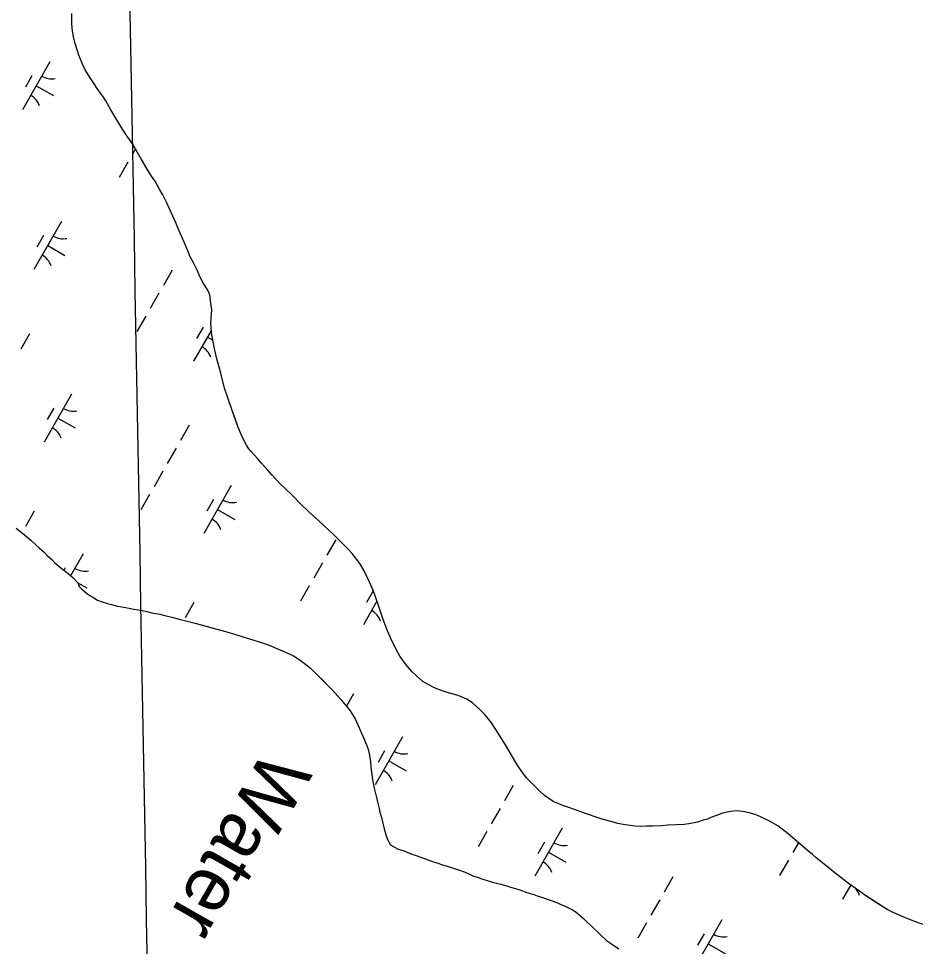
# Model space of a CAD drawing. Extents: x 3930721 to 3950824, y 220441 to 242861.
# Drawn here: x 3940727 to 3941538, y 225412 to 226251 of the extents above; entities that cross this region are included whole.
import ezdxf

# ---------------------------------------------------------------- set-up
doc = ezdxf.new("R2010")
doc.units = 0
for name, color, linetype in [('V-GRID-MAJR', 7, 'Continuous'), ('V-RIVR-IDEN', 7, 'Continuous'), ('V-TOPO-SHOR', 7, 'Continuous'), ('V-WETL-SWMP', 7, 'Continuous')]:
    doc.layers.add(name, color=color, linetype=linetype)

msp = doc.modelspace()

# ---------------------------------------------------------------- linework, layer by layer
at = {"layer": 'V-GRID-MAJR'}
msp.add_spline([(3940914.45, 221486.32), (3940866.25, 224158.18), (3940756.95, 230218.14), (3940647.64, 236278.08), (3940604.74, 238656.84)], degree=3, dxfattribs=at)
at = {"layer": 'V-TOPO-SHOR'}
for points in [[(3940937.64, 225859.68), (3940935.6, 225861.9), (3940933.36, 225865.33), (3940929.68, 225872.79), (3940925.58, 225882.08), (3940923.12, 225889.35), (3940920.65, 225896.62), (3940916.34, 225908.93), (3940913.67, 225916.81), (3940910.16, 225930.35), (3940906.44, 225944.49), (3940904.37, 225953.79), (3940901.87, 225966.92), (3940901.21, 225976.03), (3940902.16, 225987.77), (3940900.91, 225995.85), (3940900.27, 226001.11), (3940899.04, 226004.14), (3940897.21, 226007.36), (3940895.17, 226010.39), (3940893.33, 226013.61), (3940890.67, 226019.27), (3940888.83, 226023.51), (3940885.35, 226030.77), (3940882.69, 226035.61), (3940880.44, 226040.86), (3940877.16, 226048.73), (3940873.88, 226056.2), (3940871.63, 226061.24), (3940869.79, 226065.69), (3940866.92, 226072.35), (3940863.65, 226079.41), (3940861.39, 226084.26), (3940857.71, 226091.72), (3940855.26, 226096.16), (3940850.77, 226103.82), (3940847.71, 226108.46), (3940843.63, 226114.92), (3940838.32, 226124.19), (3940833.83, 226132.06), (3940830.36, 226137.71), (3940824.04, 226146.78), (3940819.96, 226153.23), (3940814.45, 226162.51), (3940810.77, 226168.35), (3940806.28, 226176.42), (3940803.63, 226180.66), (3940799.15, 226186.7), (3940795.07, 226192.95), (3940792.21, 226197.39), (3940787.72, 226204.65), (3940785.27, 226209.69), (3940781.79, 226217.77), (3940778.69, 226228.27), (3940777.46, 226233.32), (3940776.21, 226239.59), (3940775.57, 226246.06), (3940775.54, 226250.11), (3940775.72, 226255.57)], [(3941119.46, 225640.52), (3941113.99, 225642.11), (3941107.1, 225644.51), (3941102.84, 225646.1), (3941096.96, 225649.11), (3941092.9, 225651.51), (3941087.21, 225656.74), (3941083.14, 225660.36), (3941077.65, 225666.61), (3941072.14, 225674.47), (3941068.88, 225680.72), (3941063.97, 225690.61), (3941060.9, 225697.47), (3941057, 225707.77), (3941054.53, 225715.04), (3941052.06, 225722.31), (3941048.16, 225733.21), (3941045.09, 225740.89), (3941039.77, 225751.78), (3941035.89, 225758.44), (3941028.97, 225767.3), (3941024.49, 225772.14), (3941016.96, 225779.58), (3941011.68, 225784.81), (3941003.95, 225792.06), (3940998.46, 225797.09), (3940990.13, 225804.73), (3940981.59, 225812.98), (3940975.89, 225818.82), (3940967.15, 225827.27), (3940964.3, 225830.08), (3940956.57, 225838.14), (3940952.5, 225842.97), (3940947, 225849.01), (3940943.34, 225853.24), (3940940.49, 225856.66), (3940937.64, 225859.68)], [(3940725.37, 225790.38), (3940731.06, 225785.76), (3940734.72, 225782.74), (3940738.38, 225779.53), (3940743.05, 225775.1), (3940746.1, 225772.49), (3940750.57, 225768.46), (3940753.42, 225765.65), (3940757.69, 225761.62), (3940760.34, 225759.01), (3940765.62, 225754.38), (3940772.12, 225749.15), (3940776.39, 225745.54), (3940780.87, 225740.7), (3940782.3, 225737.68), (3940784.33, 225735.46), (3940788.8, 225731.64), (3940791.85, 225729.43), (3940794.49, 225727.83), (3940798.75, 225725.22), (3940801.99, 225724.02), (3940807.67, 225722.23), (3940811.32, 225721.24), (3940816.99, 225719.85), (3940820.84, 225719.06), (3940827.52, 225717.89), (3940831.77, 225717.1), (3940836.23, 225716.31), (3940843.52, 225714.94), (3940847.97, 225713.74), (3940855.06, 225712.37), (3940859.72, 225711.18), (3940867.22, 225709.4), (3940872.48, 225708.01), (3940880.99, 225706.03)], [(3940880.99, 225706.03), (3940887.07, 225704.24), (3940896.8, 225701.66), (3940906.52, 225699.08), (3940912.4, 225697.5), (3940920.71, 225695.11), (3940931.04, 225691.73), (3940936.11, 225690.14), (3940944.01, 225687.75), (3940951.1, 225685.36), (3940955.56, 225683.76), (3940961.44, 225681.17), (3940965.5, 225679.57), (3940971.99, 225676.57), (3940976.04, 225674.77), (3940981.93, 225670.96), (3940985.59, 225668.14), (3940990.87, 225663.92), (3940994.12, 225660.9), (3940998.8, 225656.28), (3941002.06, 225653.05), (3941005.31, 225649.83), (3941010.19, 225644.8), (3941013.65, 225640.98), (3941018.74, 225635.34), (3941023.62, 225629.7), (3941027.09, 225625.27), (3941031.58, 225617.81), (3941034.23, 225612.56), (3941037.51, 225604.89), (3941039.97, 225599.44), (3941043.05, 225591.36), (3941044.49, 225586.31), (3941045.54, 225579.44), (3941045.97, 225574.58), (3941046.4, 225569.33), (3941047.66, 225560.84), (3941048.9, 225555.18), (3941050.97, 225546.9), (3941052, 225542.86), (3941053.45, 225536.99), (3941054.08, 225533.56), (3941055.52, 225528.71), (3941056.35, 225524.87), (3941057.8, 225518.4), (3941059.65, 225512.14), (3941061.09, 225508.11), (3941063.74, 225503.87), (3941069.83, 225500.46), (3941076.72, 225498.27), (3941082.8, 225495.68), (3941086.85, 225494.28), (3941091.72, 225492.69), (3941095.17, 225491.29), (3941100.64, 225489.3), (3941104.49, 225488.1), (3941111.58, 225485.71), (3941116.85, 225484.12), (3941124.15, 225481.73), (3941131.04, 225479.34), (3941134.48, 225477.74), (3941138.14, 225475.94), (3941142.8, 225474.35), (3941147.05, 225472.95), (3941151.11, 225471.76), (3941155.97, 225470.17), (3941159.42, 225469.38), (3941163.26, 225468.59), (3941168.74, 225466.8), (3941172.18, 225465.8), (3941176.64, 225464.41), (3941180.49, 225463.21), (3941186.77, 225461.02), (3941193.05, 225459.03), (3941196.1, 225457.83), (3941201.16, 225456.24), (3941206.23, 225454.45), (3941209.67, 225453.25), (3941214.54, 225451.46), (3941217.58, 225450.06), (3941221.43, 225448.66), (3941228.13, 225445.26), (3941231.38, 225443.05), (3941235.64, 225439.43), (3941238.08, 225437.42), (3941241.54, 225434), (3941243.98, 225431.79), (3941246.42, 225429.37), (3941250.49, 225425.75), (3941253.54, 225422.73), (3941259.02, 225417.5), (3941263.29, 225414.49), (3941269.99, 225410.07)], [(3941467.1, 225477.07), (3941462.22, 225481.09), (3941457.34, 225485.11), (3941451.25, 225490.14), (3941448.4, 225492.15), (3941444.95, 225495.36), (3941440.27, 225499.18), (3941437.83, 225501.4), (3941433.97, 225504.61), (3941429.3, 225508.43), (3941423.2, 225513.86), (3941420.36, 225516.07), (3941416.5, 225519.09), (3941413.65, 225521.3), (3941406.15, 225525.3), (3941402.7, 225527.1), (3941397.42, 225529.71), (3941393.17, 225531.3), (3941387.7, 225532.89), (3941383.65, 225533.88), (3941377.17, 225534.66), (3941371.1, 225534.02), (3941367.87, 225533.6), (3941363.82, 225532.77), (3941358.37, 225530.51), (3941353.32, 225528.67), (3941350.09, 225527.23), (3941346.26, 225526.2), (3941341, 225524.55), (3941333.32, 225523.1), (3941329.08, 225522.27), (3941322, 225522.02), (3941314.31, 225521.78), (3941308.65, 225521.15), (3941300.36, 225520.9), (3941294.9, 225520.87), (3941289.64, 225520.64), (3941284.38, 225520.82), (3941273.85, 225522.38), (3941268.99, 225523.36), (3941264.12, 225524.76), (3941256.02, 225526.94), (3941250.35, 225528.73), (3941241.63, 225531.72), (3941235.55, 225533.91), (3941225.82, 225537.3), (3941219.54, 225539.49), (3941210.62, 225543.29), (3941202.7, 225548.71), (3941198.43, 225552.73), (3941191.31, 225559.78), (3941186.63, 225564.61), (3941182.35, 225570.25), (3941178.27, 225576.3), (3941172.76, 225585.58), (3941167.45, 225594.45), (3941163.98, 225600.1), (3941158.88, 225608.36), (3941155.01, 225614.21), (3941149.1, 225621.46), (3941144.83, 225626.09), (3941137.71, 225632.33), (3941132.64, 225635.54), (3941124.73, 225638.93), (3941119.46, 225640.52)], [(3941614.31, 225413.51), (3941604.79, 225415.48), (3941597.91, 225416.86), (3941587.57, 225419.64), (3941580.48, 225421.42), (3941570.15, 225424.2), (3941560.83, 225426.78), (3941554.75, 225428.57), (3941546.44, 225431.56), (3941540.56, 225433.56), (3941532.05, 225436.95), (3941529.21, 225437.95), (3941518.06, 225442.95), (3941513.19, 225445.14), (3941509.13, 225447.55), (3941503.04, 225451.57), (3941498.78, 225454.38), (3941492.08, 225458.79), (3941487.61, 225462), (3941480.7, 225467.02), (3941476.24, 225470.24), (3941470.75, 225474.46), (3941467.1, 225477.07)]]:
    msp.add_lwpolyline(points, dxfattribs=at)
at = {"layer": 'V-WETL-SWMP'}
for p, q in [((3940755.71, 226211.91), (3940730.86, 226168.52)), ((3940739.57, 226199.26), (3940733.61, 226188.84)), ((3940743.29, 226190.22), (3940758.91, 226181.27)), ((3940833.13, 226133.19), (3940830.27, 226128.21)), ((3940826.3, 226121.26), (3940818.35, 226107.38)), ((3940766.18, 226067.35), (3940741.34, 226023.96)), ((3940750.05, 226054.7), (3940744.08, 226044.29)), ((3940753.76, 226045.66), (3940769.38, 226036.71)), ((3940866.26, 226023.53), (3940858.31, 226009.64)), ((3940854.33, 226002.7), (3940846.38, 225988.82)), ((3940842.4, 225981.87), (3940834.45, 225967.99)), ((3940894.39, 225972.03), (3940888.42, 225961.62)), ((3940737.36, 225965.97), (3940729.41, 225952.09)), ((3940901.7, 225969.28), (3940885.68, 225941.3)), ((3940898.1, 225962.99), (3940903.17, 225960.09)), ((3940775.33, 225911.47), (3940750.48, 225868.09)), ((3940759.2, 225898.82), (3940753.23, 225888.41)), ((3940762.91, 225889.78), (3940778.53, 225880.84)), ((3940881.7, 225883.31), (3940873.75, 225869.42)), ((3940869.78, 225862.48), (3940861.82, 225848.6)), ((3940857.85, 225841.66), (3940849.9, 225827.77)), ((3940845.92, 225820.83), (3940837.97, 225806.95)), ((3940919.67, 225828.81), (3940894.83, 225785.42)), ((3940903.54, 225816.16), (3940897.57, 225805.74)), ((3940741.54, 225805.76), (3940733.59, 225791.87)), ((3940907.25, 225807.11), (3940922.87, 225798.17)), ((3941014.12, 225779.82), (3941006.17, 225765.93)), ((3940785.81, 225766.92), (3940774.49, 225747.15)), ((3940769.67, 225754.26), (3940768.44, 225752.11)), ((3941002.19, 225758.99), (3940994.24, 225745.11)), ((3940780.4, 225741.2), (3940789, 225736.28)), ((3940990.26, 225738.16), (3940982.31, 225724.28)), ((3941047.88, 225733.49), (3941041.91, 225723.08)), ((3940885.88, 225723.09), (3940877.93, 225709.21)), ((3941051.41, 225724.13), (3941039.17, 225702.75)), ((3941030.22, 225640.43), (3941023.89, 225629.36)), ((3941074.49, 225601.59), (3941049.64, 225558.2)), ((3941058.35, 225588.93), (3941052.39, 225578.52)), ((3941062.07, 225579.89), (3941077.69, 225570.95)), ((3941174.56, 225557.76), (3941166.61, 225543.87)), ((3941162.64, 225536.93), (3941154.69, 225523.05)), ((3941218.83, 225518.92), (3941193.98, 225475.53)), ((3941150.71, 225516.11), (3941142.76, 225502.22)), ((3941202.69, 225506.27), (3941196.73, 225495.85)), ((3941432.33, 225505.95), (3941427.26, 225497.11)), ((3941206.41, 225497.23), (3941222.03, 225488.28)), ((3941423.29, 225490.17), (3941415.33, 225476.28)), ((3941318.91, 225475.09), (3941310.95, 225461.21)), ((3941479.65, 225467.78), (3941472.19, 225454.76)), ((3941306.98, 225454.27), (3941299.03, 225440.38)), ((3941363.17, 225436.25), (3941338.32, 225392.86)), ((3941295.05, 225433.44), (3941287.1, 225419.56)), ((3941347.04, 225423.6), (3941341.07, 225413.19)), ((3941350.75, 225414.56), (3941366.37, 225405.61))]:
    msp.add_line(p, q, dxfattribs=at)
for points in [[(3940857.71, 226091.72), (3940855.26, 226096.16), (3940850.77, 226103.82), (3940847.71, 226108.46), (3940843.63, 226114.91), (3940838.32, 226124.19), (3940833.83, 226132.06), (3940830.36, 226137.71), (3940824.04, 226146.78), (3940819.96, 226153.23), (3940814.45, 226162.51), (3940810.77, 226168.35), (3940806.28, 226176.42), (3940803.63, 226180.66), (3940799.15, 226186.7), (3940795.07, 226192.95), (3940792.21, 226197.39), (3940787.72, 226204.65), (3940785.27, 226209.69), (3940781.79, 226217.77), (3940778.7, 226228.27), (3940777.46, 226233.32), (3940776.21, 226239.59), (3940775.57, 226246.06), (3940775.54, 226250.11), (3940775.72, 226255.57)], [(3941329.08, 225522.27), (3941322, 225522.03), (3941314.31, 225521.78), (3941308.65, 225521.15), (3941300.36, 225520.9), (3941294.9, 225520.87), (3941289.64, 225520.64), (3941284.38, 225520.82), (3941273.85, 225522.38), (3941268.99, 225523.36), (3941264.12, 225524.76), (3941256.02, 225526.94), (3941250.35, 225528.73), (3941241.63, 225531.72), (3941235.55, 225533.91), (3941225.82, 225537.3), (3941219.54, 225539.49), (3941210.62, 225543.29), (3941202.7, 225548.71), (3941198.43, 225552.73), (3941191.31, 225559.78), (3941186.63, 225564.61), (3941182.35, 225570.25), (3941178.27, 225576.3), (3941172.76, 225585.57), (3941167.45, 225594.45), (3941163.98, 225600.09), (3941158.88, 225608.36), (3941155.01, 225614.21), (3941149.1, 225621.46), (3941144.83, 225626.09), (3941137.71, 225632.33), (3941132.64, 225635.54), (3941124.73, 225638.93), (3941119.46, 225640.52), (3941113.99, 225642.11), (3941107.1, 225644.51), (3941102.84, 225646.1), (3941096.96, 225649.11), (3941092.9, 225651.51), (3941087.21, 225656.74), (3941083.14, 225660.36), (3941077.65, 225666.61), (3941072.15, 225674.47), (3941068.88, 225680.72), (3941063.97, 225690.61), (3941060.9, 225697.47), (3941057, 225707.77), (3941052.06, 225722.31), (3941048.16, 225733.21), (3941045.09, 225740.89), (3941039.77, 225751.78), (3941035.89, 225758.44), (3941028.97, 225767.3), (3941024.49, 225772.14), (3941011.68, 225784.81), (3941003.95, 225792.06), (3940998.46, 225797.08), (3940990.13, 225804.73), (3940981.58, 225812.98), (3940975.89, 225818.82), (3940967.15, 225827.27), (3940964.3, 225830.08), (3940956.57, 225838.14), (3940952.5, 225842.97), (3940947, 225849.01), (3940943.34, 225853.24), (3940940.49, 225856.66), (3940937.64, 225859.68), (3940935.6, 225861.9), (3940933.36, 225865.33), (3940929.68, 225872.79), (3940925.58, 225882.08), (3940920.65, 225896.62), (3940916.34, 225908.94), (3940913.67, 225916.81), (3940910.16, 225930.35), (3940906.44, 225944.49), (3940904.37, 225953.79), (3940901.87, 225966.92), (3940901.21, 225976.02), (3940902.16, 225987.76), (3940900.91, 225995.85), (3940900.27, 226001.11), (3940899.04, 226004.14), (3940897.21, 226007.36), (3940895.17, 226010.39), (3940893.33, 226013.61), (3940890.67, 226019.27), (3940888.83, 226023.5), (3940885.35, 226030.77), (3940882.69, 226035.61), (3940880.44, 226040.86), (3940877.16, 226048.73), (3940873.88, 226056.2), (3940871.63, 226061.25), (3940869.79, 226065.69), (3940866.92, 226072.35), (3940863.65, 226079.41), (3940861.39, 226084.26), (3940857.71, 226091.72)], [(3940725.37, 225790.38), (3940731.06, 225785.76), (3940734.72, 225782.74), (3940738.38, 225779.53), (3940743.05, 225775.1), (3940746.1, 225772.49), (3940750.57, 225768.46), (3940753.42, 225765.65), (3940757.69, 225761.62), (3940760.33, 225759.01), (3940765.62, 225754.38), (3940772.12, 225749.15), (3940776.39, 225745.54), (3940780.87, 225740.7), (3940782.3, 225737.68), (3940784.33, 225735.46), (3940788.8, 225731.64), (3940791.85, 225729.43), (3940794.49, 225727.83), (3940798.75, 225725.22), (3940801.99, 225724.02), (3940807.67, 225722.23), (3940811.32, 225721.24), (3940816.99, 225719.85), (3940820.84, 225719.06), (3940827.52, 225717.89), (3940831.77, 225717.1), (3940836.23, 225716.31), (3940843.52, 225714.94), (3940847.97, 225713.74), (3940855.06, 225712.37), (3940859.72, 225711.18), (3940867.22, 225709.4), (3940872.48, 225708.01), (3940880.99, 225706.03), (3940887.07, 225704.24), (3940906.52, 225699.08), (3940912.4, 225697.5), (3940920.7, 225695.11), (3940931.04, 225691.73), (3940936.11, 225690.14), (3940944.01, 225687.75), (3940951.1, 225685.36), (3940955.56, 225683.76), (3940961.44, 225681.17), (3940965.5, 225679.57), (3940971.99, 225676.57), (3940976.04, 225674.77), (3940981.93, 225670.96), (3940985.59, 225668.14), (3940990.87, 225663.92), (3940994.12, 225660.9), (3941005.31, 225649.83), (3941010.19, 225644.8), (3941013.65, 225640.98)], [(3941013.65, 225640.98), (3941018.74, 225635.34), (3941023.62, 225629.7), (3941027.09, 225625.27), (3941031.58, 225617.81), (3941034.23, 225612.56), (3941037.51, 225604.89), (3941039.97, 225599.44), (3941043.05, 225591.36), (3941044.49, 225586.31), (3941045.54, 225579.44), (3941045.97, 225574.59), (3941046.4, 225569.33), (3941047.66, 225560.84), (3941048.9, 225555.18), (3941050.97, 225546.9), (3941052, 225542.86), (3941053.45, 225536.99), (3941054.07, 225533.56), (3941055.52, 225528.71), (3941056.35, 225524.87), (3941057.8, 225518.4), (3941059.65, 225512.14), (3941061.09, 225508.1), (3941063.74, 225503.87), (3941069.83, 225500.46), (3941076.72, 225498.27), (3941082.8, 225495.68), (3941086.85, 225494.28), (3941091.72, 225492.69), (3941095.17, 225491.29), (3941100.64, 225489.3), (3941104.49, 225488.1), (3941111.58, 225485.71), (3941116.85, 225484.12), (3941124.15, 225481.73), (3941131.04, 225479.34), (3941134.49, 225477.74), (3941138.14, 225475.94), (3941142.8, 225474.35), (3941147.05, 225472.95), (3941151.11, 225471.76), (3941155.97, 225470.17), (3941159.42, 225469.38), (3941163.26, 225468.59), (3941168.73, 225466.79), (3941172.18, 225465.8), (3941176.64, 225464.41), (3941180.49, 225463.21), (3941186.77, 225461.02), (3941193.05, 225459.03), (3941196.1, 225457.83), (3941201.16, 225456.24), (3941206.23, 225454.45), (3941209.67, 225453.25), (3941214.54, 225451.46), (3941217.58, 225450.06), (3941221.43, 225448.66), (3941228.13, 225445.26), (3941231.38, 225443.05), (3941235.64, 225439.43), (3941238.08, 225437.42), (3941241.54, 225434), (3941243.98, 225431.79), (3941246.42, 225429.37), (3941250.48, 225425.75), (3941253.54, 225422.73), (3941259.02, 225417.5), (3941263.29, 225414.49), (3941269.99, 225410.07)], [(3941540.56, 225433.55), (3941532.05, 225436.95), (3941529.21, 225437.95), (3941518.06, 225442.95), (3941513.19, 225445.14), (3941509.13, 225447.55), (3941492.08, 225458.79), (3941487.61, 225462), (3941480.7, 225467.02), (3941476.24, 225470.24), (3941470.75, 225474.46), (3941467.1, 225477.07), (3941451.25, 225490.14), (3941448.4, 225492.14), (3941444.95, 225495.36), (3941440.27, 225499.18), (3941437.83, 225501.4), (3941433.97, 225504.61), (3941429.3, 225508.43), (3941423.2, 225513.86), (3941420.36, 225516.07), (3941416.5, 225519.09), (3941413.65, 225521.3), (3941406.15, 225525.3), (3941402.7, 225527.11), (3941397.42, 225529.71), (3941393.17, 225531.3), (3941387.7, 225532.89), (3941383.64, 225533.88), (3941377.17, 225534.66), (3941371.1, 225534.02), (3941367.87, 225533.6), (3941363.82, 225532.77), (3941358.37, 225530.51), (3941353.32, 225528.67), (3941350.1, 225527.23), (3941346.26, 225526.2), (3941341, 225524.55), (3941333.32, 225523.1), (3941329.08, 225522.27)]]:
    msp.add_lwpolyline(points, dxfattribs=at)
for centre, start, end in [((3940757.22, 226214.07), 239.42788, 280.97154), ((3940729.76, 226166.13), 19.42788, 60.97154), ((3940767.69, 226069.51), 239.42788, 280.97154), ((3940740.24, 226021.57), 19.42788, 60.97154), ((3940884.58, 225938.91), 19.42788, 60.97154), ((3940776.84, 225913.63), 239.42788, 280.97154), ((3940749.39, 225865.69), 19.42788, 60.97154), ((3940921.18, 225830.97), 239.42788, 280.97154), ((3940893.73, 225783.03), 19.42788, 60.97154), ((3940787.32, 225769.07), 239.42788, 280.97154), ((3941038.07, 225700.36), 19.42788, 60.97154), ((3941076, 225603.74), 239.42788, 280.97154), ((3941048.54, 225555.8), 19.42788, 60.97154), ((3941220.34, 225521.08), 239.42788, 280.97154), ((3941192.89, 225473.14), 19.42788, 60.97154), ((3941471.09, 225452.36), 60.66066, 60.97154), ((3941471.09, 225452.36), 19.42788, 47.4678), ((3941364.68, 225438.41), 239.42788, 280.97154)]:
    msp.add_arc(centre, 17.62, start, end, dxfattribs=at)

# ---------------------------------------------------------------- texts
at = {"layer": 'V-RIVR-IDEN'}
msp.add_text('Water', height=50, rotation=240.19966, dxfattribs=at).set_placement((3940950.14, 225592.15))

doc.saveas('drawing.dxf')
